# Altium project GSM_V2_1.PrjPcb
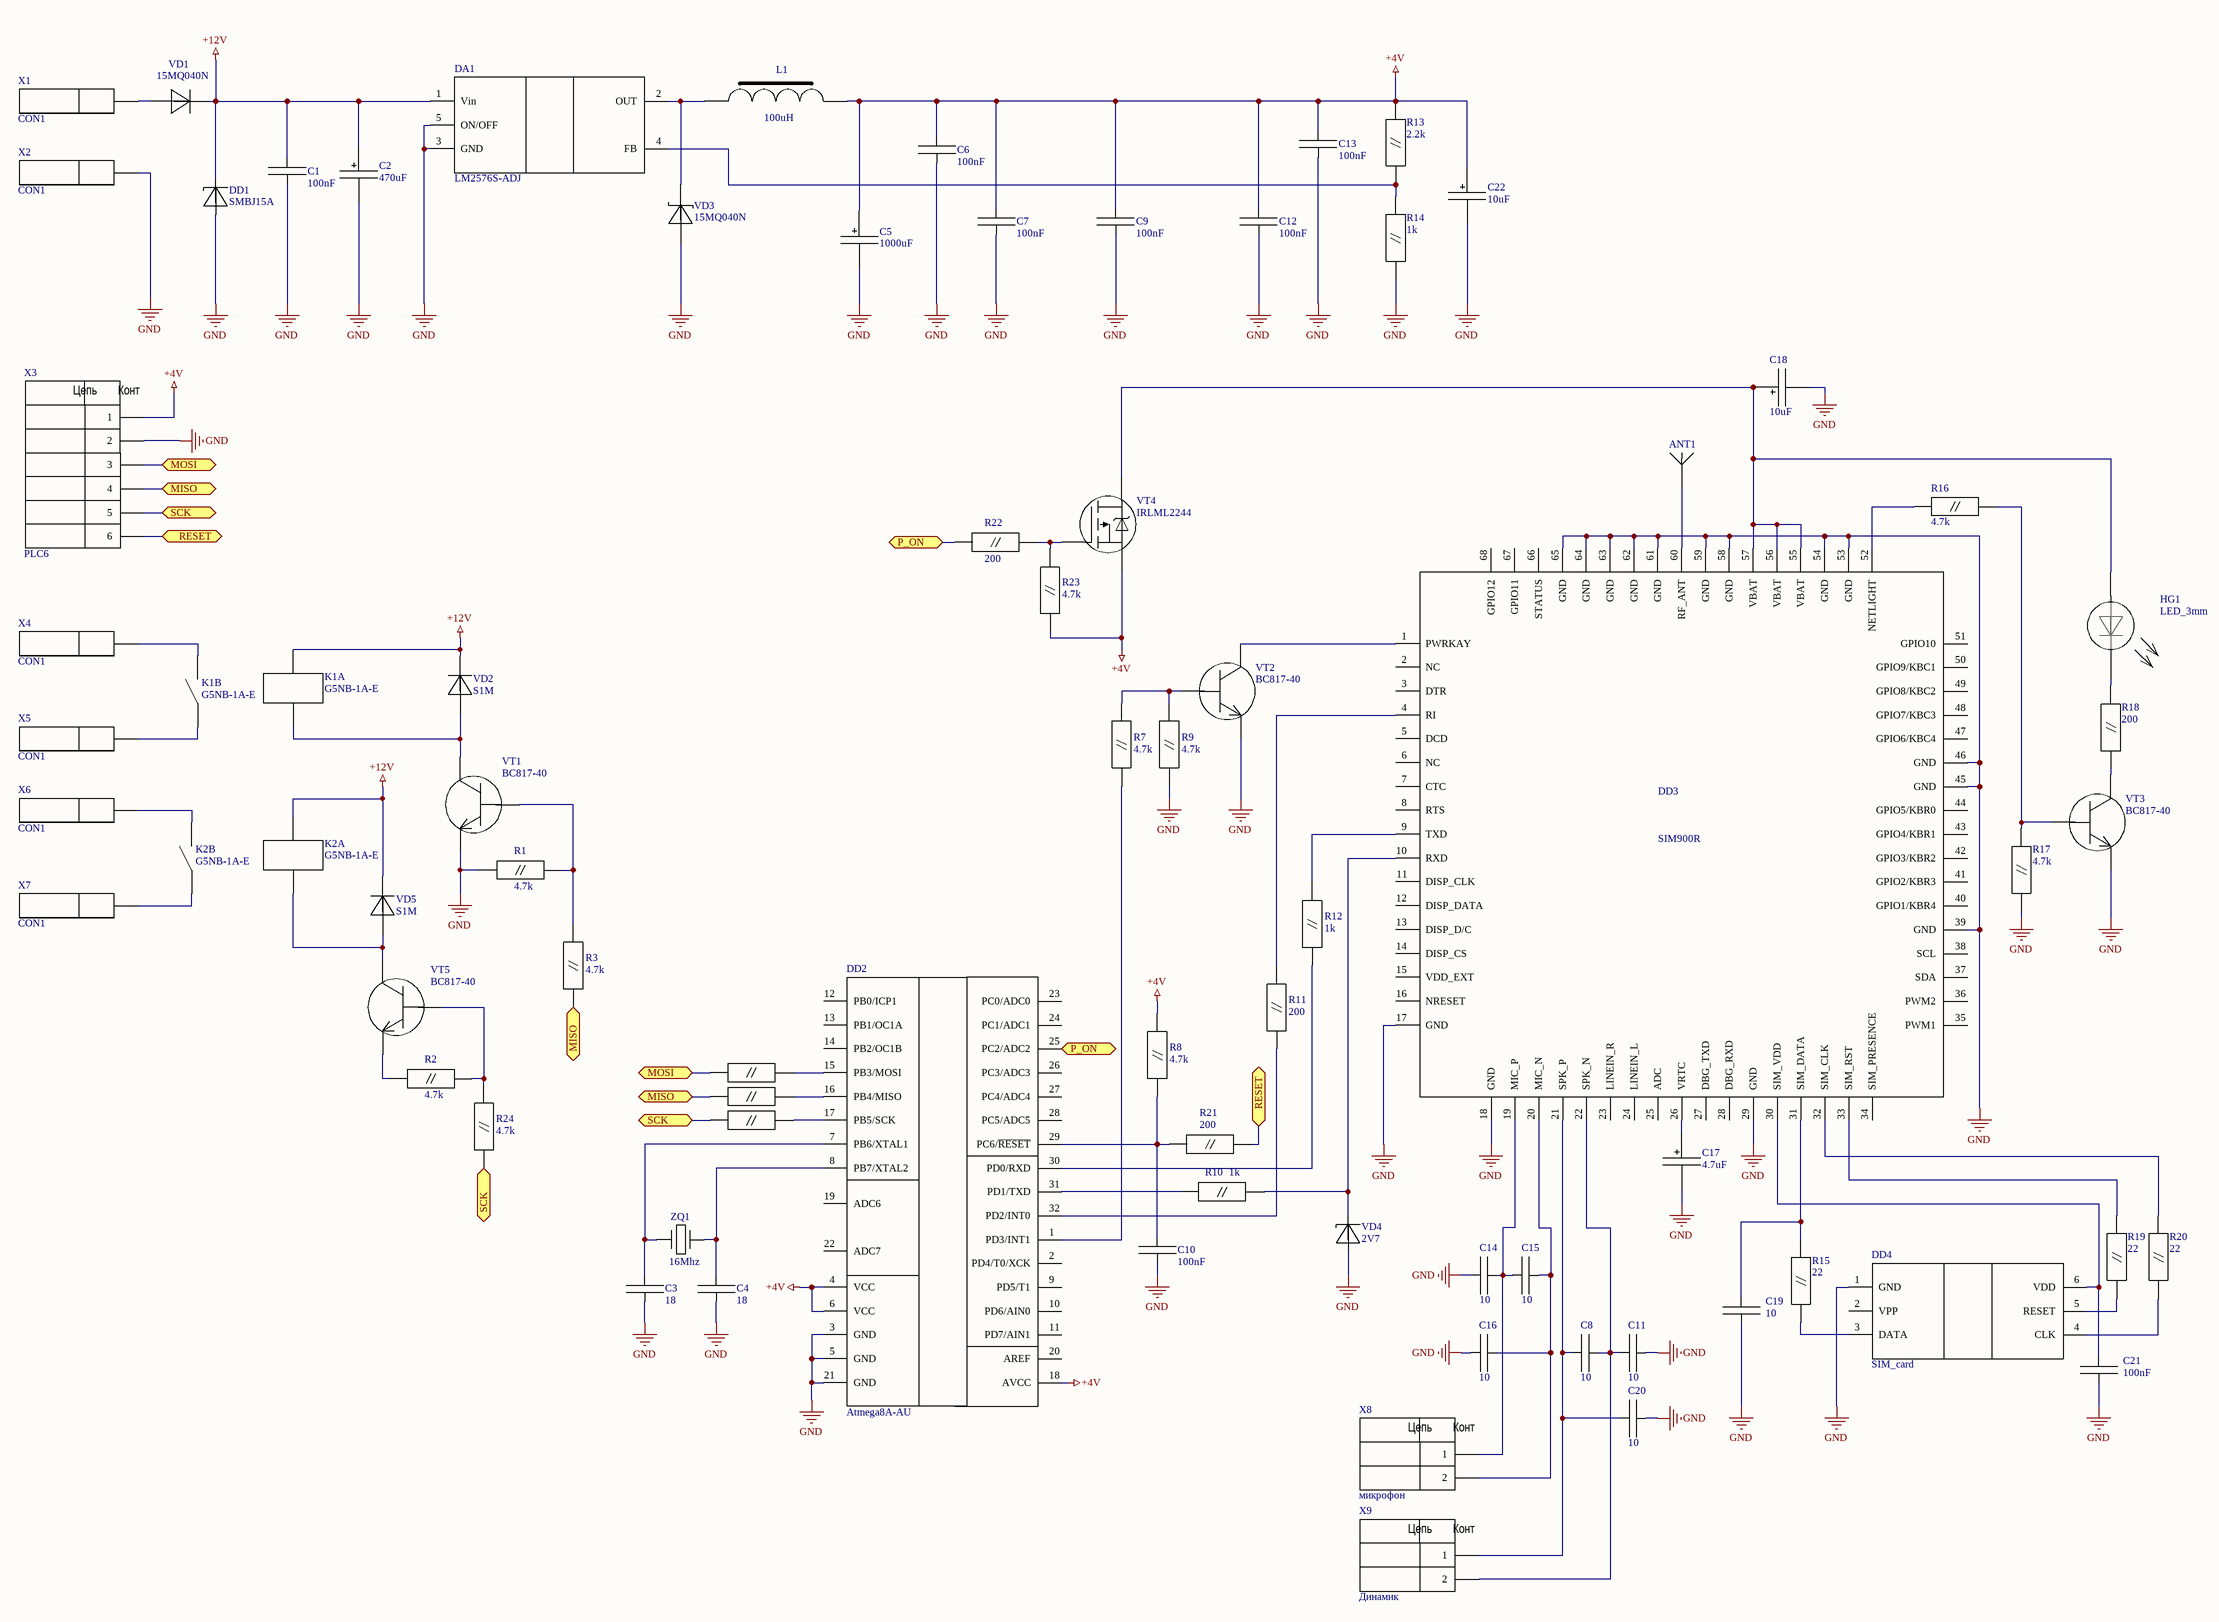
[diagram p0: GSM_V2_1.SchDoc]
1 sheet, 76 parts. Net scope: flat (ports and power ports of the same name join across sheets).
Board file: GSM_V2_1.PcbDoc

## Sheet GSM_V2_1.SchDoc
size A2

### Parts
ANT1  ANT  [ANTENNA]  (value not drawn)
C1  100nF  [1206_CAP]
C2  470uF  [3mm]
C3  18  [0805]
C4  18  [0805]
C5  1000uF  [3mm]
C6  100nF  [1206_CAP]
C7  100nF  [0805]
C8  10  [0805]
C9  100nF  [1206_CAP]
C10  100nF  [1206_CAP]
C11  10  [0805]
C12  100nF  [1206_CAP]
C13  100nF  [1206_CAP]
C14  10  [0805]
C15  10  [0805]
C16  10  [0805]
C17  4.7uF  [A]
C18  10uF  [A]
C19  10  [0805]
C20  10  [0805]
C21  100nF  [0805]
C22  10uF  [A]
DA1  LM2576S-ADJ  [D2PAK-5]
DD1  SMBJ15A  [SMB(DO-214AA)]
DD2  Atmega8A-AU  [TQFP32]
DD3  SIM900R  [SIM900]
DD4  SIM_card  [6393699-1]
HG1  LED_3mm  [1206_CAP]
K1  G5NB-1A-E  [G5NB-1A-E]  (parts A,B of 2)
K2  G5NB-1A-E  [G5NB-1A-E]  (parts A,B of 2)
L1  100uH  [B82477G4]
R1  4.7k  [0805]
R2  4.7k  [0805]
R3  4.7k  [0805]
R4  200  [0805]  (value not drawn)
R5  200  [0805]  (value not drawn)
R6  200  [0805]  (value not drawn)
R7  4.7k  [0805]
R8  4.7k  [1206]
R9  4.7k  [0805]
R10  1k  [0805]
R11  200  [0805]
R12  1k  [0805]
R13  2.2k  [1206]
R14  1k  [1206]
R15  22  [1206]
R16  4.7k  [1206]
R17  4.7k  [0805]
R18  200  [1206]
R19  22  [1206]
R20  22  [1206]
R21  200  [0805]
R22  200  [0805]
R23  4.7k  [0805]
R24  4.7k  [0805]
VD1  15MQ040N  [SMA(DO-214AC)]
VD2  S1M  [SMA(DO-214AC)]
VD3  15MQ040N  [SMA(DO-214AC)]
VD4  2V7  [SOD80]
VD5  S1M  [SMA(DO-214AC)]
VT1  BC817-40  [SOT23]
VT2  BC817-40  [SOT23]
VT3  BC817-40  [SOT23]
VT4  IRLML2244  [SOT23]
VT5  BC817-40  [SOT23]
X1  CON1  [ZL201-1G]
X2  CON1  [ZL201-1G]
X3  PLC6  [ZL201-6G]
X4  CON1  [ZL201-1G]
X5  CON1  [ZL201-1G]
X6  CON1  [ZL201-1G]
X7  CON1  [ZL201-1G]
X8  микрофон  [ZL201-2G]
X9  Динамик  [ZL201-2G]
ZQ1  16Mhz  [CRUSTAL]

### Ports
MISO, MOSI, P_ON, RESET, SCK

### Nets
+4V: C5.2 C6.1 C7.1 C9.1 C12.1 C13.1 C22.2 DD2.4(VCC) DD2.6(VCC) DD2.18(AVCC) L1.2 R8.1 R13.2 R23.2 VT4.2(S) X3.1
+12V: C1.1 C2.2 DA1.1(Vin) DD1.2 K1.1 K2.1 VD1.2 VD2.2 VD5.2
GND: ANT1.2 C1.2 C2.1 C3.1 C4.1 C5.1 C6.2 C7.2 C9.2 C10.2 C11.2 C12.2 C13.2 C14.2 C16.1 C17.1 C18.1 C19.1 C20.2 C21.1 C22.1 DA1.3(GND) DA1.5(ON/OFF) DD1.1 DD2.3(GND) DD2.5(GND) DD2.21(GND) DD3.17(GND) DD3.18(GND) DD3.29(GND) DD3.39(GND) DD3.45(GND) DD3.46(GND) DD3.53(GND) DD3.54(GND) DD3.58(GND) DD3.59(GND) DD3.61(GND) DD3.62(GND) DD3.63(GND) DD3.64(GND) DD3.65(GND) DD4.1(GND) R1.1 R9.1 R14.1 R17.1 VD3.1 VD4.1 VT1.2(E) VT2.2(E) VT3.2(E) X2.1 X3.2
NetANT1_1: ANT1.1 DD3.60(RF_ANT)
NetC3_2: C3.2 DD2.7(PB6/XTAL1) ZQ1.2
NetC4_2: C4.2 DD2.8(PB7/XTAL2) ZQ1.1
NetC8_1: C8.1 C20.1 DD3.21(SPK_P) X9.1
NetC8_2: C8.2 C11.1 DD3.22(SPK_N) X9.2
NetC10_1: C10.1 DD2.29(PC6/~{RESET}) R8.2 R21.2
NetC14_1: C14.1 C15.2 DD3.19(MIC_P) X8.1
NetC15_1: C15.1 C16.2 DD3.20(MIC_N) X8.2
NetC17_2: C17.2 DD3.26(VRTC)
NetC18_2: C18.2 DD3.55(VBAT) DD3.56(VBAT) DD3.57(VBAT) HG1.1 VT4.3(D)
NetC19_2: C19.2 DD3.31(SIM_DATA) R15.2
NetC21_2: C21.2 DD3.30(SIM_VDD) DD4.6(VDD)
NetDA1_2: DA1.2(OUT) L1.1 VD3.2
NetDA1_4: DA1.4(FB) R13.1 R14.2
NetDD2_1: DD2.1(PD3/INT1) R7.1
NetDD2_15: DD2.15(PB3/MOSI) R4.1
NetDD2_16: DD2.16(PB4/MISO) R5.1
NetDD2_17: DD2.17(PB5/SCK) R6.1
NetDD2_25: DD2.25(PC2/ADC2) R22.2 ; port P_ON
NetDD2_30: DD2.30(PD0/RXD) R12.2
NetDD2_31: DD2.31(PD1/TXD) R10.2
NetDD2_32: DD2.32(PD2/INT0) R11.2
NetDD3_1: DD3.1(PWRKAY) VT2.3(C)
NetDD3_4: DD3.4(RI) R11.1
NetDD3_9: DD3.9(TXD) R12.1
NetDD3_10: DD3.10(RXD) R10.1 VD4.2
NetDD3_32: DD3.32(SIM_CLK) R20.2
NetDD3_33: DD3.33(SIM_RST) R19.2
NetDD3_52: DD3.52(NETLIGHT) R16.2
NetDD4_3: DD4.3(DATA) R15.1
NetDD4_4: DD4.4(CLK) R20.1
NetDD4_5: DD4.5(RESET) R19.1
NetHG1_2: HG1.2 R18.1
NetK1_2: K1.2 X4.1
NetK1_3: K1.3 X5.1
NetK1_4: K1.4 VD2.1 VT1.3(C)
NetK2_2: K2.2 X6.1
NetK2_3: K2.3 X7.1
NetK2_4: K2.4 VD5.1 VT5.3(C)
NetR1_2: R1.2 R3.1 VT1.1(B)
NetR2_1: R2.1 VT5.2(E)
NetR2_2: R2.2 R24.1 VT5.1(B)
NetR3_2: R3.2 R5.2 X3.4 ; port MISO
NetR4_2: R4.2 X3.3 ; port MOSI
NetR6_2: R6.2 R24.2 X3.5 ; port SCK
NetR7_2: R7.2 R9.2 VT2.1(B)
NetR16_1: R16.1 R17.2 VT3.1(B)
NetR18_2: R18.2 VT3.3(C)
NetR21_1: R21.1 X3.6 ; port RESET
NetR22_1: R22.1 R23.1 VT4.1(G)
NetVD1_1: VD1.1 X1.1

Not connected (* = marked no-connect by the designer): DD2 2(PD4/T0/XCK) 9(PD5/T1) 10(PD6/AIN0) 11(PD7/AIN1) 12(PB0/ICP1) 13(PB1/OC1A) 14(PB2/OC1B) 19(ADC6) 20(AREF) 22(ADC7) 23(PC0/ADC0) 24(PC1/ADC1) 26(PC3/ADC3) 27(PC4/ADC4) 28(PC5/ADC5); DD3 2(NC) 3(DTR) 5(DCD) 6(NC) 7(CTC) 8(RTS) 11(DISP_CLK) 12(DISP_DATA) 13(DISP_D/C) 14(DISP_CS) 15(VDD_EXT) 16(NRESET) 23(LINEIN_R) 24(LINEIN_L) 25(ADC) 27(DBG_TXD) 28(DBG_RXD) 34(SIM_PRESENCE) 35(PWM1) 36(PWM2) 37(SDA) 38(SCL) 40(GPIO1/KBR4) 41(GPIO2/KBR3) 42(GPIO3/KBR2) 43(GPIO4/KBR1) 44(GPIO5/KBR0) 47(GPIO6/KBC4) 48(GPIO7/KBC3) 49(GPIO8/KBC2) 50(GPIO9/KBC1) 51(GPIO10) 66(STATUS) 67(GPIO11) 68(GPIO12); DD4 2(VPP)

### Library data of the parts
C1 C3 C4 C6-C16 C19-C21 = CAP
C2 C5 = CAP_POL
C17 C18 C22 = tantalum
DA1 = LM2576-ADJ: Step-Down  Switching Regulator
DD1 = SMBJ15A: Защитный диод
DD2 = Atmega8A-AU: 8 KB Flash, 8-chennel ADC
DD3 = SIM900R: GSM/GPRS
K1 K2 = G5NB-1A-E: РЕЛЕ
L1 = INDUCTOR
R1-R24 = res_0.125
VD1 VD2 VD5 = 1N4007
VD4 = ZENER DIOD
VT1-VT3 VT5 = BC817: N-P-N
VT4 = IRLML2244: P-Channel  -20 V -4.3A
X8 X9 = PLC2
ZQ1 = CRYSTAL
